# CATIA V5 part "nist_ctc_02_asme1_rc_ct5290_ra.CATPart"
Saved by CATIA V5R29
Part number: NIST Test Case 02 CATIA V5R29 RB
Revision: B
Nomenclature: Test Case 2 Baseline
Property "Modeled By": "Rich Eckenrode, RECON Services.com - Revised by DS"
Property "CAGE Code": "64JW1"
Property "Company": "RECON Services Incorporated"
Bounding box of the stored display mesh (mm): x -340 to 340, y -40 to 820, z -360 to 40
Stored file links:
  E:\users\dgn\TPS V5\Import-export annotations\Step\PMI representation 2015\NIST UC\CTC\nist_ctc_02_asme1_ct5210_rc - V5R29.CATPart
  C:\Program Files\Dassault Systemes\B21\win_b64\reffiles\standard\MetricThickPitch.txt
  E:\users\dgn\TPS V5\Import-export annotations\Step\PMI representation 2015\NIST UC\CTC\nist_ctc_02_asme1_ct5210_rc.CATPart
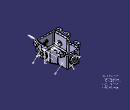
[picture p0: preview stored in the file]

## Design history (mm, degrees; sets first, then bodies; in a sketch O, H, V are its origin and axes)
TTRSSet1
f4a2d38f3ddc11d3a929006094b99c4b_11 "CATTPSSet"
Set1 "MBD_AB"
  Point1: (0, 695.6661, 0), in AxisSystem2
  Point2: (-180, 65.6661, 0), in AxisSystem2
  Point3: (180, 65.6661, 0), in AxisSystem2
  Point4 to Point7: stored without definition
  Point8 "Point.4-c1": (0, 0, -50), in AxisSystem2
Set2 "MBD_A"
  Sketch1 on face of Pad1 from Sketch3.L1, origin (0, 0, 0), H (1, 0, 0), V (0, -0.0349, 0.9994)
    line L1 (180, -29.9817) -> (180, -99.9817)
    point P1 (180, -29.9817)
    length L1 = 70
    distance V L1 = 180
    distance H P1 = 29.9817
    vertical: L1 V
Set3 "MBD_B"
  Point9: type Center, Curve edge of Split1
  AxisSystem1: origin (0, 812, -140), X (1, 0, 0), Y (0, 0, -1), Z (0, 1, 0)
  Sketch2 on face of Hole3, origin (0, 812, 0), H (-1, 0, 0), V (0, 0, 1)
    circle A1 centre (0, -140) radius 42.5
    point P1 (0, -140)
    radius A1 = 42.5
    coincidence: P1 V
  Fill1: Boundary Sketch2
  Split1: ToCut Fill1, Cutting edge [face of Hole3 | face of Hole3]
Set4 "MBD_ABC"
  AxisSystem2: origin (0, 9.7778, -330), X (-1, 0, 0), Y (0, 1, 0), Z (0, 0, -1)
Set5 "MBD_C"
  Point10: type Center, Curve edge [face of Mirror1 | face of Mirror1]
  AxisSystem3: origin (302, 97, 40), X (0, -1, 0), Y (1, 0, 0), Z (0, 0, 1)
  Point11: type Center, Curve edge [face of Pad1 | face of Hole10]
  AxisSystem4: origin (-150, 755, 0), X (0, -1, 0), Y (1, 0, 0), Z (0, 0, 1)
Body1 (main body)
  Sketch3 on xy-plane, origin (0, 0, 0), H (1, 0, 0), V (0, 1, 0)
    point P1 (-250, 0)
    line L1 (-250, 0) -> (250, 0)
    line L2 (250, 0) -> (250, 400)
    line L3 (-250, 400) -> (-250, 0)
    line L4 (-175, 780) -> (175, 780)
    line L5 (175, 780) -> (175, 530)
    line L6 (-175, 530) -> (-175, 780)
    line L7 (175, 530) -> (250, 400)
    line L8 (-250, 400) -> (-175, 530)
    distance L3 L2 = 500
    distance L3 V = 250
    length L2 = 400
    length L3 = 400
    distance L6 L5 = 350
    distance L6 V = 175
    length L5 = 250
    length L6 = 250
    distance L4 L1 = 780
    coincidence: P1 H
    horizontal: L1 H, L4 H
    vertical: L2 V, L3 V, L5 V, L6 V
  Pad1: profile Sketch3, direction (0, 0, -1), length 330
  Draft1: Angle -2, Neutral start face of Pad1, PullDir start face of Pad1, SupportToDraft (face of Pad1 from Sketch3.L1; face of Pad1 from Sketch3.L2; face of Pad1 from Sketch3.L7; face of Pad1 from Sketch3.L5; face of Pad1 from Sketch3.L4; face of Pad1 from Sketch3.L6; face of Pad1 from Sketch3.L8; face of Pad1 from Sketch3.L3)
  Shell1: ExtOffset 0, Face start face of Pad1, IntOffset 40
  Sketch4 on zx-plane, origin (0, 0, 0), H (-1, 0, 0), V (0, 0, 1)
    circle A1 centre (0, -140) radius 100
    point P1 (0, -140)
    distance P1 H = 140
    radius A1 = 100
    coincidence: P1 V
  Sketch5 on yz-plane, origin (0, 0, 0), H (0, 1, 0), V (0, 0, 1)
    point P1 (200, -185)
    ellipse A1 centre (200, -185) semi-axes 120, 90 rotation 0
    distance P1 H = 185
    "Radius" A1 = 120
    distance P1 V = 200
  Pad2: profile Sketch4, direction along zx-plane reversed, length 40, opposite side length 20
  Pad3: profile Sketch4, direction (0, 1, 0), length 750, opposite side length -820
  Pad4: profile Sketch5, direction (1, 0, 0), length 230, opposite side length -265
  Pad5: profile Sketch5, direction (1, 0, 0), length -230, opposite side length 265
  Sketch6 on start face of Pad1, origin (0, 0, 0), H (1, 0, 0), V (0, 1, 0)
    line L1 (-163, 707.9854) -> (-265, 690)
    point P2 (-265, 690)
    line L2 (-265, 690) -> (-265, 574)
    line L3 (-265, 574) -> (-163, 556.0146)
    line L4 (-163, 556.0146) -> (-163, 707.9854)
    line L5 (-235, 368.5143) -> (-340, 350)
    point P5 (-340, 350)
    line L6 (-340, 350) -> (-340, 260)
    point P6 (-340, 260)
    line L7 (-340, 260) -> (-305, 253.8286)
    line L8 (-305, 253.8286) -> (-305, 146.1714)
    line L9 (-305, 146.1714) -> (-340, 140)
    point P9 (-340, 140)
    line L10 (-340, 140) -> (-340, 50)
    line L11 (-340, 50) -> (-235, 31.4857)
    circle A1 centre (-227, 635) radius 11
    point P11 (-227, 635)
    reference projected line E1 (-100, -40) -> (100, -40) from edge [end face of Pad2 | face of Pad2 from Sketch4.A1]
    line L12 (-235, 368.5143) -> (-235, 31.4857)
    circle A2 centre (-302, 302) radius 11
    point P14 (-302, 302)
    circle A3 centre (-302, 97) radius 11
    point P15 (-302, 97)
    reference projected line E2 (-250, 0) -> (250, 0) from edge [face of Pad1 from Sketch3.L1 | start face of Pad1]
    distance P9 P6 = 120
    length L2 = 116
    length L6 = 90
    length L10 = 90
    distance H P5 = 350
    distance H P2 = 690
    angle L1 L2 = 100
    angle L2 L3 = 100
    distance E1 P11 = 675
    distance V P11 = 227
    radius A1 = 11
    distance V L2 = 265
    distance V L6 = 340
    angle L5 L6 = 100
    angle L6 L7 = 100
    angle L9 L10 = 100
    angle L10 L11 = 100
    distance L6 L8 = 35
    distance V P15 = 302
    distance V P14 = 302
    distance P14 P15 = 205
    radius A2 = 11
    radius A3 = 11
    distance P15 E2 = 97
    distance V L12 = 235
    distance V L4 = 163
    vertical: L2 V, L4 V, L6 V, L8 V, L10 V, L12 V
    coincidence: P9 L6
  Pad6: profile Sketch6, direction (0, 0, 1), length 40, mirrored extent
  Draft2: Angle 5, Neutral face of Pad6 from Sketch6.L10, PullDir face of Pad6 from Sketch6.L10, SupportToDraft start face of Pad6
  Draft3: Angle 5, Neutral face of Pad6 from Sketch6.L2, PullDir face of Pad6 from Sketch6.L10, SupportToDraft start face of Pad6
  Mirror1: of Pad6, Draft2, Draft3, about yz-plane
  Sketch7 on start face of Pad1, origin (0, 0, 0), H (1, 0, 0), V (0, 1, 0)
    line L1 (-195, 728.4018) -> (195, 728.4018)
    line L2 (195, 524.7588) -> (-195, 524.7588)
    line L3 (-195, 524.7588) -> (-195, 728.4018)
    line L4 (-270, 397.2577) -> (270, 397.2577)
    line L5 (270, -27.7368) -> (-270, -27.7368)
    line L6 (-270, -27.7368) -> (-270, 397.2577)
    line L7 (195, 524.7588) -> (195, 728.4018)
    line L8 (270, -27.7368) -> (270, 397.2577)
    distance V L3 = 195
    distance V L6 = 270
    horizontal: L1 H, L2 H, L4 H, L5 H
    vertical: L3 V, L6 V
    symmetry: L3 L7 V, L6 L8 V
  Pocket1: profile Sketch7, direction (0, 0, 1), through (limit type 6)
  Draft4: Angle 3, Neutral end face of Pad6, PullDir edge [face of Mirror1 | face of Mirror1], SupportToDraft (face of Pad6 from Sketch6.L1; face of Pad6 from Sketch6.L2; face of Pad6 from Sketch6.L3; face of Pad6 from Sketch6.L5; face of Pad6 from Sketch6.L6; face of Pad6 from Sketch6.L8; face of Pad6 from Sketch6.L9; face of Pad6 from Sketch6.L10; face of Pad6 from Sketch6.L7; face of Pad6 from Sketch6.L11; face of Mirror1; face of Mirror1; face of Mirror1; face of Mirror1; face of Mirror1; face of Mirror1; face of Mirror1; face of Mirror1; face of Mirror1; face of Mirror1)
  Sketch8 on face of Pocket1, origin (0, 0, 0), H (1, 0, 0), V (0, 1, 0)
    construction line L1 (-309.7798, 20) -> (337.0255, 20)
    point P3 (35, 20)
    point P4 (110, 20)
    point P5 (185, 20)
    construction line L2 (230, 491.1929) -> (230, -71.1929)
    construction line L3 (207.3038, 760) -> (-244.515, 760)
    axis line L4 (155, 816.2891) -> (155, 460.0193)
    point P12 (230, 60)
    point P13 (230, 135)
    point P14 (230, 210)
    point P15 (230, 285)
    point P16 (230, 360)
    point P17 (155, 560)
    point P18 (155, 635)
    point P19 (155, 710)
    point P20 (110, 760)
    point P21 (35, 760)
    point P22 (207, 435)
    point P23 (169, 500)
    point P24 (-35, 20)
    point P25 (-110, 20)
    point P26 (-185, 20)
    point P27 (-230, 60)
    point P28 (-230, 135)
    point P29 (-230, 210)
    point P30 (-230, 285)
    point P31 (-230, 360)
    point P32 (-155, 560)
    point P33 (-155, 635)
    point P34 (-155, 710)
    point P35 (-110, 760)
    point P36 (-35, 760)
    point P37 (-207, 435)
    point P38 (-169, 500)
    distance L1 H = 20
    distance V P3 = 35
    distance V P4 = 110
    distance V P5 = 185
    distance V L2 = 230
    distance V L4 = 155
    distance V P21 = 35
    distance V P20 = 110
    distance L1 P12 = 40
    distance L1 P13 = 115
    distance L1 P14 = 190
    distance L1 P15 = 265
    distance L1 P16 = 340
    distance L1 P22 = 415
    distance L1 P23 = 480
    distance L1 P17 = 540
    distance L1 P18 = 615
    distance L1 P19 = 690
    distance V P22 = 207
    distance V P23 = 169
    distance L1 L3 = 740
    horizontal: L1 H, L3 H
    coincidence: P3 L1, P4 L1, P5 L1, P12 L2, P13 L2, P15 L2, P16 L2, P17 L4, P18 L4, P19 L4, P20 L3, P21 L3
    vertical: L2 V, L4 V
    midpoint: P14 L2
    symmetry: P3 P24 V, P4 P25 V, P5 P26 V, P12 P27 V, P13 P28 V, P14 P29 V, P15 P30 V, P16 P31 V, P17 P32 V, P18 P33 V, P19 P34 V, P20 P35 V, P21 P36 V, P22 P37 V, P23 P38 V
  Sketch9 on xy-plane, origin (35, 0, 0), H (1, 0, 0), V (0, 1, 0)
    point P1 (0, 20)
    reference projected point E1 (0, 20) from Sketch8.P3
    coincidence: E1 P1
  Hole1: placed by Sketch9, at (35, 20, 0) direction (0, 0, -1), diameter 10.1, depth 30, V-bottom angle 118
  UserPattern1: of Hole1, copies 30, at the points of Sketch8
  Sketch10 on end face of Pad2, origin (0, -40, -140), H (1, 0, 0), V (0, 0, 1)
    point P1 (0, 0)
    reference intersected line E1 through (0, 0) direction (0, 1) from yz-plane
    reference intersected line E2 through (0, 140) direction (-1, 0) from xy-plane
    distance E1 P1 = 0
    distance E2 P1 = 140
  Hole2: placed by Sketch10, at (0, -40, -140) direction (0, 1, 0), diameter 40, depth 100, counterbore diameter 120, counterbore depth 8
  Sketch11 on start face of Pad3, origin (0, 820, -140), H (1, 0, 0), V (0, 0, -1)
    point P1 (0, 0)
    reference intersected line E1 through (0, 0) direction (0, 1) from yz-plane
    reference intersected line E2 through (0, -140) direction (1, 0) from xy-plane
    distance P1 E1 = 0
    distance E2 P1 = 140
  Hole3: placed by Sketch11, at (0, 820, -140) direction (0, -1, 0), diameter 40, depth 100, counterbore diameter 120, counterbore depth 8
  Sketch12 on face of Hole2, origin (0, -32, 0), H (1, 0, 0), V (0, 0, 1)
    circle A1 centre (0, -140) radius 57.5
    point P1 (0, -140)
    radius A1 = 57.5
    distance H P1 = 140
    coincidence: P1 V
  Pocket2: profile Sketch12, direction (0, 1, 0), length 57, opposite side length -100
  Pocket3: profile Sketch12, direction (0, -1, 0), length -700, opposite side length 787
  Sketch13 on start face of Pocket3, origin (0, 755, 0), H (1, 0, 0), V (0, 0, 1)
    circle A1 centre (0, -140) radius 37.5
    point P1 (0, -140)
    distance P1 H = 140
    radius A1 = 37.5
    coincidence: P1 V
  Pocket4: profile Sketch13, direction (0, 1, 0), length 8
  Sketch14 on end face of Pocket2, origin (0, 25, 0), H (-1, 0, 0), V (0, 0, 1)
    circle A1 centre (0, -140) radius 37.5
    point P1 (0, -140)
    distance P1 H = 140
    radius A1 = 37.5
    coincidence: P1 V
  Pocket5: profile Sketch14, direction (0, -1, 0), length 8
  Sketch15 on start face of Pad4, origin (265, 195.5622, -179.7588), H (0, 1, 0), V (0, 0, 1)
    point P1 (4.4378, -5.2412)
    reference intersected line E1 through (-195.5622, 0) direction (0, 1) from zx-plane
    reference intersected line E2 through (0, 179.7588) direction (-1, 0) from xy-plane
    distance P1 E1 = 200
    distance E2 P1 = 185
  Hole4: placed by Sketch15, at (265, 200, -185) direction (-1, 0, 0), diameter 52, depth 100, counterbore diameter 100, counterbore depth 8
  Sketch16 on start face of Pad5, origin (-265, 207.8851, -185), H (0, 1, 0), V (0, 0, -1)
    point P1 (-7.8851, 0)
    reference intersected line E1 through (0, -185) direction (1, 0) from xy-plane
    reference intersected line E2 through (-207.8851, 0) direction (0, 1) from zx-plane
    distance P1 E1 = 185
    distance E2 P1 = 200
  Hole5: placed by Sketch16, at (-265, 200, -185) direction (1, 0, 0), diameter 52, depth 100, counterbore diameter 100, counterbore depth 8
  Sketch17 on face of Hole5, origin (-257, 0, 0), H (0, -1, 0), V (0, 0, 1)
    circle A1 centre (-200, -185) radius 57.5
    point P1 (-200, -185)
    radius A1 = 57.5
    distance V P1 = 200
    distance H P1 = 185
  Pocket6: profile Sketch17, direction (-1, 0, 0), length -32, opposite side length 100
  Pocket7: profile Sketch17, direction (-1, 0, 0), length -400, opposite side length 482
  Plane1: type Offset, RefPlane zx-plane, Offset 200
  Plane2: type Offset, RefPlane xy-plane, Offset -185
  Sketch18 on start face of Pad4, origin (265, 0, 0), H (0, 1, 0), V (0, 0, 1)
    point P1 (112, -185)
    point P2 (126.83, -145)
    point P3 (171.1, -117)
    point P4 (228.9, -117)
    point P5 (273.17, -145)
    point P6 (288, -185)
    point P7 (273.17, -225)
    point P8 (228.9, -253)
    point P9 (171.1, -253)
    point P10 (126.83, -225)
    reference intersected line E1 through (0, -185) direction (-1, 0) from Plane2
    reference intersected line E2 through (0, -185) direction (-1, 0) from Plane2
    reference intersected line E3 through (0, -185) direction (-1, 0) from Plane2
    reference intersected line E4 through (0, -185) direction (-1, 0) from Plane2
    reference intersected line E5 through (0, -185) direction (-1, 0) from Plane2
    reference intersected line E6 through (0, -185) direction (-1, 0) from Plane2
    reference intersected line E7 through (0, -185) direction (-1, 0) from Plane2
    reference intersected line E8 through (0, -185) direction (-1, 0) from Plane2
    reference intersected line E9 through (0, -185) direction (-1, 0) from Plane2
    reference intersected line E10 through (0, -185) direction (-1, 0) from Plane2
    reference intersected line E11 through (200, 0) direction (0, 1) from Plane1
    reference intersected line E12 through (200, 0) direction (0, 1) from Plane1
    reference intersected line E13 through (200, 0) direction (0, 1) from Plane1
    reference intersected line E14 through (200, 0) direction (0, 1) from Plane1
    reference intersected line E15 through (200, 0) direction (0, 1) from Plane1
    reference intersected line E16 through (200, 0) direction (0, 1) from Plane1
    reference intersected line E17 through (200, 0) direction (0, 1) from Plane1
    reference intersected line E18 through (200, 0) direction (0, 1) from Plane1
    reference intersected line E19 through (200, 0) direction (0, 1) from Plane1
    reference intersected line E20 through (200, 0) direction (0, 1) from Plane1
    distance E1 P1 = 0
    distance E2 P6 = 0
    distance E3 P5 = 40
    distance E4 P7 = 40
    distance E5 P4 = 68
    distance E6 P8 = 68
    distance E7 P9 = 68
    distance E8 P10 = 40
    distance E9 P2 = 40
    distance E10 P3 = 68
    distance E11 P4 = 28.9
    distance E12 P3 = 28.9
    distance E13 P2 = 73.17
    distance E14 P1 = 88
    distance E15 P5 = 73.17
    distance E16 P6 = 88
    distance E17 P7 = 73.17
    distance E18 P8 = 28.9
    distance E19 P9 = 28.9
    distance E20 P10 = 73.17
  Sketch19 on start face of Pad4, origin (265, 296.9999, -181.291), H (0, 1, 0), V (0, 0, 1)
    point P1 (-8.9999, -3.709)
    reference projected point E1 (-8.9999, -3.709) from Sketch18.P6
    coincidence: E1 P1
  Hole6: placed by Sketch19, at (265, 288, -185) direction (-1, 0, 0), diameter 8.38, depth 25, V-bottom angle 118
  UserPattern2: of Hole6, copies 10, at the points of Sketch18
  Sketch20 on start face of Pad5, origin (-265, 288, -185), H (0, 1, 0), V (0, 0, -1)
    point P1 (0, 0)
    reference projected point E1 (0, 0) from Sketch18.P6
    coincidence: E1 P1
  Hole7: placed by Sketch20, at (-265, 288, -185) direction (1, 0, 0), diameter 8.38, depth 25, V-bottom angle 118
  UserPattern3: of Hole7, copies 10, at the points of Sketch18
  Draft5: Angle 3, Neutral end face of Pad2, PullDir end face of Pad2, SupportToDraft face of Pad2 from Sketch4.A1
  Draft6: Angle 3, Neutral start face of Pad3, PullDir start face of Pad3, SupportToDraft face of Pad3 from Sketch4.A1
  Draft7: Angle 3, Neutral start face of Pad5, PullDir start face of Pad5, SupportToDraft face of Pad5 from Sketch5.A1
  Draft8: Angle 3, Neutral start face of Pad4, PullDir start face of Pad4, SupportToDraft face of Pad4 from Sketch5.A1
  Sketch21 on end face of Pad1, origin (0, 0, -330), H (1, 0, 0), V (0, -1, 0)
    line L1 (-135, -115) -> (135, -115)
    line L2 (135, -115) -> (135, -365)
    line L3 (-135, -365) -> (-135, -115)
    line L4 (-82.5, -465) -> (82.5, -465)
    point P5 (-82.5, -465)
    line L5 (135, -365) -> (82.5, -465)
    line L6 (-135, -365) -> (-82.5, -465)
    line L7 (-89.0832, -355.6518) -> (-57.5481, -415.7187)
    point P7 (-95.1571, -344.0825)
    point P8 (-42.6571, -444.0825)
    construction line L8 (-135, -365) -> (-95.1571, -344.0825)
    construction line L9 (-82.5, -465) -> (-42.6571, -444.0825)
    line L10 (89.0832, -355.6518) -> (57.5481, -415.7187)
    point P9 (95.1571, -344.0825)
    point P10 (42.6571, -444.0825)
    construction line L11 (135, -365) -> (95.1571, -344.0825)
    construction line L12 (82.5, -465) -> (42.6571, -444.0825)
    line L13 (-50.4649, -420) -> (50.4649, -420)
    point P11 (-82.5, -420)
    point P12 (82.5, -420)
    construction line L14 (-82.5, -465) -> (-82.5, -420)
    construction line L15 (82.5, -465) -> (82.5, -420)
    line L16 (90, -351.9332) -> (90, -168)
    point P13 (90, -365)
    point P14 (90, -115)
    construction line L17 (135, -365) -> (90, -365)
    construction line L18 (135, -115) -> (90, -115)
    line L19 (-82, -160) -> (82, -160)
    line L20 (-90, -168) -> (-90, -351.9332)
    point P15 (-90, -115)
    point P16 (-90, -365)
    construction line L21 (-135, -115) -> (-90, -115)
    construction line L22 (-135, -365) -> (-90, -365)
    arc A1 centre (-82, -351.9332) radius 8 from (-90, -351.9332) to (-89.0832, -355.6518) ccw
    arc A2 centre (-50.4649, -412) radius 8 from (-57.5481, -415.7187) to (-50.4649, -420) ccw
    arc A3 centre (50.4649, -412) radius 8 from (50.4649, -420) to (57.5481, -415.7187) ccw
    arc A4 centre (82, -351.9332) radius 8 from (90, -351.9332) to (89.0832, -355.6518) cw
    arc A5 centre (82, -168) radius 8 from (90, -168) to (82, -160) ccw
    arc A6 centre (-82, -168) radius 8 from (-82, -160) to (-90, -168) ccw
    length L2 = 250
    distance L1 L4 = 350
    length L3 = 250
    distance L3 L2 = 270
    distance V L2 = 135
    length L4 = 165
    distance V P5 = 82.5
    distance L6 L7 = 45
    distance L5 L10 = 45
    distance L4 L13 = 45
    distance L2 L16 = 45
    distance L3 L20 = 45
    distance L1 L19 = 45
    radius A1 = 8
    radius A2 = 8
    radius A3 = 8
    radius A4 = 8
    radius A5 = 8
    radius A6 = 8
    distance L1 H = 115
    horizontal: L1 H, L4 H
    vertical: L2 V, L3 V
    perpendicularity: L8 L6, L8 L7, L9 L6, L9 L7, L11 L5, L11 L10, L12 L5, L12 L10, L14 L4, L14 L13, L15 L4, L15 L13, L17 L2, L17 L16, L18 L2, L18 L16, L21 L3, L21 L20, L22 L3, L22 L20
    coincidence: P13 L16, P9 L10, P10 L10, P12 L13, P11 L13, P8 L7, P7 L7, P16 L20, P15 L20, P14 L16
    tangency: A1 L20, A1 L7, A2 L7, A2 L13, A3 L13, A3 L10, A4 L16, A4 L10, A5 L16, A5 L19, A6 L19, A6 L20
  Pad7: profile Sketch21, direction (0, 0, -1), length 30
  Sketch22 on end face of Pad7, origin (0, 0, -360), H (1, 0, 0), V (0, -1, 0)
    line L1 (91, -141) -> (-91, -141)
    line L2 (109, -159) -> (109, -354.1521)
    line L3 (55.9048, -439) -> (-55.9048, -439)
    line L4 (-109, -354.1521) -> (-109, -159)
    reference projected line E1 (135, -115) -> (-135, -115) from edge [face of Pad7 | face of Pad7]
    reference projected line E2 (135, -365) -> (135, -115) from edge [face of Pad7 | face of Pad7]
    reference projected line E3 (-82.5, -465) -> (82.5, -465) from edge [face of Pad7 | face of Pad7]
    reference projected line E4 (-135, -115) -> (-135, -365) from edge [face of Pad7 | face of Pad7]
    line L5 (106.9372, -362.5191) -> (71.842, -429.367)
    line L6 (-71.842, -429.367) -> (-106.9372, -362.5191)
    reference projected line E5 (82.5, -465) -> (135, -365) from edge [face of Pad7 | face of Pad7]
    reference projected line E6 (-135, -365) -> (-82.5, -465) from edge [face of Pad7 | face of Pad7]
    arc A1 centre (91, -159) radius 18 from (109, -159) to (91, -141) ccw
    arc A2 centre (-91, -159) radius 18 from (-91, -141) to (-109, -159) ccw
    arc A3 centre (-91, -354.1521) radius 18 from (-109, -354.1521) to (-106.9372, -362.5191) ccw
    arc A4 centre (-55.9048, -421) radius 18 from (-71.842, -429.367) to (-55.9048, -439) ccw
    arc A5 centre (55.9048, -421) radius 18 from (55.9048, -439) to (71.842, -429.367) ccw
    arc A6 centre (91, -354.1521) radius 18 from (106.9372, -362.5191) to (109, -354.1521) ccw
    line L7 (101, -159) -> (101, -354.1521)
    point P19 (101, -159)
    point P20 (101, -354.1521)
    construction line L8 (109, -159) -> (101, -159)
    construction line L9 (109, -354.1521) -> (101, -354.1521)
    line L10 (91, -149) -> (-91, -149)
    point P21 (91, -149)
    point P22 (-91, -149)
    construction line L11 (91, -141) -> (91, -149)
    construction line L12 (-91, -141) -> (-91, -149)
    line L13 (-101, -354.1521) -> (-101, -159)
    point P23 (-101, -354.1521)
    point P24 (-101, -159)
    construction line L14 (-109, -354.1521) -> (-101, -354.1521)
    construction line L15 (-109, -159) -> (-101, -159)
    line L16 (-64.7588, -425.6483) -> (-99.854, -358.8004)
    point P25 (-64.7588, -425.6483)
    point P26 (-99.854, -358.8004)
    construction line L17 (-71.842, -429.367) -> (-64.7588, -425.6483)
    construction line L18 (-106.9372, -362.5191) -> (-99.854, -358.8004)
    line L19 (55.9048, -431) -> (-55.9048, -431)
    point P27 (55.9048, -431)
    point P28 (-55.9048, -431)
    construction line L20 (55.9048, -439) -> (55.9048, -431)
    construction line L21 (-55.9048, -439) -> (-55.9048, -431)
    line L22 (99.854, -358.8004) -> (64.7588, -425.6483)
    point P29 (99.854, -358.8004)
    point P30 (64.7588, -425.6483)
    construction line L23 (106.9372, -362.5191) -> (99.854, -358.8004)
    construction line L24 (71.842, -429.367) -> (64.7588, -425.6483)
    arc A7 centre (91, -159) radius 10 from (101, -159) to (91, -149) ccw
    arc A8 centre (-91, -159) radius 10 from (-91, -149) to (-101, -159) ccw
    arc A9 centre (-91, -354.1521) radius 10 from (-101, -354.1521) to (-99.854, -358.8004) ccw
    arc A10 centre (-55.9048, -421) radius 10 from (-64.7588, -425.6483) to (-55.9048, -431) ccw
    arc A11 centre (55.9048, -421) radius 10 from (55.9048, -431) to (64.7588, -425.6483) ccw
    arc A12 centre (91, -354.1521) radius 10 from (101, -354.1521) to (99.854, -358.8004) cw
    distance E1 L1 = 26
    distance E2 L2 = 26
    distance L3 E3 = 26
    distance L4 E4 = 26
    distance E5 L5 = 26
    distance L6 E6 = 26
    radius A1 = 18
    radius A2 = 18
    radius A3 = 18
    radius A5 = 18
    radius A6 = 18
    distance L2 L7 = 8
    distance L1 L10 = 8
    distance L4 L13 = 8
    distance L6 L16 = 8
    distance L3 L19 = 8
    distance L5 L22 = 8
    radius A7 = 10
    radius A8 = 10
    radius A9 = 10
    radius A10 = 10
    radius A11 = 10
    radius A12 = 10
    radius A4 = 18
    horizontal: L1 H, L3 H
    vertical: L2 V, L4 V
    tangency: A1 L2, A1 L1, A2 L1, A2 L4, A3 L4, A3 L6, A4 L6, A4 L3, A5 L3, A5 L5, A6 L5, A6 L2, A7 L7, A8 L10, A8 L13, A9 L13, A9 L16, A10 L16, A10 L19, A11 L19, A11 L22, A12 L7, A12 L22
    perpendicularity: L8 L2, L8 L7, L9 L2, L9 L7, L11 L1, L11 L10, L12 L1, L12 L10, L14 L4, L14 L13, L15 L4, L15 L13, L17 L6, L17 L16, L18 L6, L18 L16, L20 L3, L20 L19, L21 L3, L21 L19, L23 L5, L23 L22, L24 L5, L24 L22
    coincidence: P19 L7, P21 L10, L10 P22, L13 P24, L13 P23, L16 P26, L16 P25, L19 P28, L19 P27, L22 P30, L7 P20, L22 P29
  Pocket8: profile Sketch22, direction (0, 0, 1), length 8
  Sketch23 on end face of Pad7, origin (0, 0, -360), H (1, 0, 0), V (0, -1, 0)
    construction line L1 (147.8122, -128) -> (-168.3513, -128)
    construction line L2 (122, -83.3568) -> (122, -419.3374)
    construction line L3 (-122, -77.561) -> (-122, -413.5541)
    construction line L4 (122, -452) -> (-122, -452)
    point P7 (122, -452)
    point P8 (-122, -452)
    reference projected line E1 (109, -354.1521) -> (109, -159) from edge [end face of Pad7 | face of Pocket8 from Sketch22.L2]
    reference projected line E2 (-109, -159) -> (-109, -354.1521) from edge [end face of Pad7 | face of Pocket8 from Sketch22.L4]
    reference projected line E3 (-55.9048, -439) -> (55.9048, -439) from edge [end face of Pad7 | face of Pocket8 from Sketch22.L3]
    reference projected line E4 (91, -141) -> (-91, -141) from edge [end face of Pad7 | face of Pocket8 from Sketch22.L1]
    point P9 (25, -128)
    point P10 (74, -128)
    point P11 (122, -128)
    point P12 (-25, -128)
    point P13 (-74, -128)
    point P14 (-122, -128)
    point P15 (-122, -176)
    point P16 (-122, -224)
    point P17 (-122, -272)
    point P18 (-122, -320)
    point P19 (-25, -452)
    point P20 (25, -452)
    point P21 (122, -320)
    point P22 (122, -272)
    point P23 (122, -224)
    point P24 (122, -176)
    construction line L5 (0, -44.6123) -> (0, -544.8239)
    point P25 (0, -44.6123)
    point P27 (74.6423, -452)
    point P28 (122, -361.795)
    point P29 (97.9523, -407.6)
    point P30 (-74.6423, -452)
    point P31 (-122, -361.795)
    point P32 (-97.9523, -407.6)
    reference projected line E5 (91, -141) -> (-91, -141) from edge [end face of Pad7 | face of Pocket8 from Sketch22.L1]
    reference projected line E6 (91, -141) -> (-91, -141) from edge [end face of Pad7 | face of Pocket8 from Sketch22.L1]
    distance E1 L2 = 13
    distance L3 E2 = 13
    distance E3 L4 = 13
    distance E4 L1 = 13
    distance P11 P24 = 48
    distance P24 P23 = 48
    distance P23 P22 = 48
    distance P22 P21 = 48
    distance P14 P15 = 48
    distance P15 P16 = 48
    distance P16 P17 = 48
    distance P17 P18 = 48
    distance L5 P20 = 25
    distance L5 P19 = 25
    distance L5 P9 = 25
    distance L5 P12 = 25
    distance L5 P13 = 74
    distance L5 P10 = 74
    distance E5 P32 = 266.6
    distance P29 E6 = 266.6
    distance L5 P32 = 97.9523
    distance L5 P29 = 97.9523
    distance P21 P28 V = 41.795
    distance P31 P18 = 41.795
    distance P27 L2 = 47.3577
    distance L3 P30 = 47.3577
    horizontal: L1 H, L4 H
    vertical: L2 V, L3 V, L5 V
    coincidence: P7 L2, P8 L3, P9 L1, P10 L1, P11 L2, P11 L1, P12 L1, P13 L1, P14 L3, P14 L1, P15 L3, P16 L3, P17 L3, P18 L3, P19 L4, P20 L4, P21 L2, P22 L2, P23 L2, P24 L2, P25 V, P27 L4, P28 L2, P30 L4, P31 L3
  Sketch24 on end face of Pad7, origin (122, 111.7735, -360), H (1, 0, 0), V (0, -1, 0)
    point P1 (0, -16.2265)
    reference projected point E1 (0, -16.2265) from Sketch23.P11
    coincidence: E1 P1
  Hole8: placed by Sketch24, at (122, 128, -360) direction (0, 0, 1), diameter 8.38, depth 25, V-bottom angle 118
  UserPattern4: of Hole8, copies 22, at the points of Sketch23
  Sketch25 on end face of Pad1, origin (0, 0, -330), H (1, 0, 0), V (0, -1, 0)
    arc A1 centre (0, -286) radius 60 from (35, -334.734) to (35, -237.266) ccw
    point P1 (0, -286)
    line L1 (-20, -196) -> (20, -196)
    line L2 (35, -211) -> (35, -237.266)
    line L3 (-35, -237.266) -> (-35, -211)
    line L4 (35, -334.734) -> (35, -361)
    line L5 (20, -376) -> (-20, -376)
    line L6 (-35, -361) -> (-35, -334.734)
    point P2 (35, -376)
    arc A2 centre (0, -286) radius 60 from (-35, -237.266) to (-35, -334.734) ccw
    arc A3 centre (-20, -361) radius 15 from (-35, -361) to (-20, -376) ccw
    arc A4 centre (20, -361) radius 15 from (20, -376) to (35, -361) ccw
    arc A5 centre (20, -211) radius 15 from (35, -211) to (20, -196) ccw
    arc A6 centre (-20, -211) radius 15 from (-20, -196) to (-35, -211) ccw
    reference projected line E1 (91, -141) -> (-91, -141) from edge [end face of Pad7 | face of Pocket8 from Sketch22.L1]
    radius A3 = 15
    radius A4 = 15
    radius A5 = 15
    radius A6 = 15
    distance L6 L4 = 70
    distance L2 L3 = 70
    distance L1 L5 = 180
    radius A2 = 60
    distance L1 P1 = 90
    distance E1 L1 = 55
    distance V L2 = 35
    coincidence: P1 V, P2 L2, A1 A2, L5 P2, L4 P2
    horizontal: L1 H, L5 H
    vertical: L2 V, L3 V, L4 V, L6 V
    tangency: A3 L6, A3 L5, A4 L5, A4 L4, A5 L2, A5 L1, A6 L1, A6 L3
  Pocket9: profile Sketch25, direction (0, 0, 1), length 100
  Draft9: Angle 3, Neutral end face of Pad7, PullDir end face of Pad7, SupportToDraft (face of Pad7 from Sketch21.L2; face of Pad7 from Sketch21.L5; face of Pad7 from Sketch21.L4; face of Pad7 from Sketch21.L6; face of Pad7 from Sketch21.L3; face of Pad7 from Sketch21.L1; face of Pad7 from Sketch21.L13)
  Fillet1: radius 25, on edge [face of Pad1 from Sketch3.L5 | end face of Pad1]; edge [face of Pad1 from Sketch3.L7 | end face of Pad1]; edge [face of Pad1 from Sketch3.L2 | end face of Pad1]; edge [face of Pad1 from Sketch3.L1 | end face of Pad1]; edge [face of Pad1 from Sketch3.L3 | end face of Pad1]; edge [face of Pad1 from Sketch3.L8 | end face of Pad1]; edge [face of Pad1 from Sketch3.L6 | end face of Pad1]; edge [face of Pad1 from Sketch3.L4 | end face of Pad1]; edge [face of Pad1 from Sketch3.L5 | face of Pad1 from Sketch3.L4]; edge [face of Pad1 from Sketch3.L5 | face of Pad1 from Sketch3.L7]; edge [face of Pad1 from Sketch3.L2 | face of Pad1 from Sketch3.L7]; edge [face of Pad1 from Sketch3.L1 | face of Pad1 from Sketch3.L2]; edge [face of Pad1 from Sketch3.L3 | face of Pad1 from Sketch3.L1]; edge [face of Pad1 from Sketch3.L8 | face of Pad1 from Sketch3.L3]; edge [face of Pad1 from Sketch3.L8 | face of Pad1 from Sketch3.L6]; edge [face of Pad1 from Sketch3.L4 | face of Pad1 from Sketch3.L6]; edge [face of Shell1 | face of Shell1] (x16)
  Fillet2: radius 8, on edge [face of Pad7 from Sketch21.L16 | end face of Pad1]
  Fillet3: radius 10, on edge [face of Pad5 from Sketch5.A1 | face of Pad1 from Sketch3.L3]; edge [face of Pad2 from Sketch4.A1 | face of Pad1 from Sketch3.L1]; edge [face of Pad4 from Sketch5.A1 | face of Pad1 from Sketch3.L2]; edge [face of Pad3 from Sketch4.A1 | face of Pad1 from Sketch3.L4]; edge [face of Pad6 from Sketch6.L1 | face of Pad1 from Sketch3.L6]; edge [start face of Pad6 | face of Pad1 from Sketch3.L6]; edge [face of Pad6 from Sketch6.L1 | start face of Pad6]; edge [face of Pad6 from Sketch6.L2 | face of Pad6 from Sketch6.L1]; edge [face of Pad6 from Sketch6.L2 | start face of Pad6]; edge [face of Pad6 from Sketch6.L3 | face of Pad6 from Sketch6.L2]; edge [face of Pad6 from Sketch6.L3 | face of Pad1 from Sketch3.L6]; edge [face of Pad6 from Sketch6.L5 | face of Pad1 from Sketch3.L3]; edge [start face of Pad6 | face of Pad1 from Sketch3.L3]; edge [face of Pad6 from Sketch6.L5 | start face of Pad6]; edge [face of Pad6 from Sketch6.L6 | face of Pad6 from Sketch6.L5]; edge [face of Pad6 from Sketch6.L6 | start face of Pad6]; edge [face of Pad6 from Sketch6.L7 | face of Pad6 from Sketch6.L6]; edge [face of Pad6 from Sketch6.L7 | start face of Pad6]; edge [face of Pad6 from Sketch6.L7 | face of Pad6 from Sketch6.L8]; edge [start face of Pad6 | face of Pad6 from Sketch6.L8]; edge [face of Pad6 from Sketch6.L9 | face of Pad6 from Sketch6.L8]; edge [face of Pad6 from Sketch6.L9 | start face of Pad6]; edge [face of Pad6 from Sketch6.L10 | face of Pad6 from Sketch6.L9]; edge [face of Pad6 from Sketch6.L10 | start face of Pad6]; edge [face of Pad6 from Sketch6.L11 | face of Pad6 from Sketch6.L10]; edge [face of Pad6 from Sketch6.L11 | face of Pad1 from Sketch3.L3]; edge [face of Mirror1 | face of Pad1 from Sketch3.L2] (x3); edge [face of Mirror1 | face of Mirror1] (x18); edge [face of Mirror1 | face of Pad1 from Sketch3.L5] (x3); edge [face of Pad6 from Sketch6.L3 | start face of Pad6]; edge [face of Pad6 from Sketch6.L11 | start face of Pad6]
  Sketch26 on face of Mirror1, origin (0, 0, 40), H (1, 0, 0), V (0, 1, 0)
    reference projected circle E1 centre (302, 97) radius 11 from edge [face of Mirror1 | face of Mirror1]
    reference projected circle E2 centre (302, 302) radius 11 from edge [face of Mirror1 | face of Mirror1]
    reference projected circle E3 centre (227, 635) radius 11 from edge [face of Mirror1 | face of Mirror1]
    reference projected circle E4 centre (-227, 635) radius 11 from edge [end face of Pad6 | face of Pad6 from Sketch6.A1]
    reference projected circle E5 centre (-302, 302) radius 11 from edge [end face of Pad6 | face of Pad6 from Sketch6.A2]
    reference projected circle E6 centre (-302, 97) radius 11 from edge [end face of Pad6 | face of Pad6 from Sketch6.A3]
    circle A1 centre (302, 97) radius 30
    point P1 (302, 97)
    circle A2 centre (302, 302) radius 30
    point P2 (302, 302)
    circle A3 centre (227, 635) radius 30
    point P3 (227, 635)
    circle A4 centre (-227, 635) radius 30
    point P4 (-227, 635)
    circle A5 centre (-302, 302) radius 30
    point P5 (-302, 302)
    circle A6 centre (-302, 97) radius 30
    point P6 (-302, 97)
    radius A1 = 30
    radius A2 = 30
    radius A3 = 30
    radius A4 = 30
    radius A5 = 30
    radius A6 = 30
    concentricity: P1 E1, P2 E2, P3 E3, P4 E4, P5 E5, P6 E6
  Pocket10: profile Sketch26, direction (0, 0, -1), length 200, opposite side length -81
  Fillet4: radius 6, on edge [face of Pocket1 from Sketch7.L6 | face of Pad1]; edge [face of Pocket1 from Sketch7.L3 | face of Pad1]; edge [face of Pocket1 from Sketch7.L8 | face of Pad1]; edge [face of Pocket1 from Sketch7.L7 | face of Pad1]
  Fillet5: radius 10, on edge [face of Pad7 from Sketch21.L3 | end face of Pad1]; edge [face of Pad7 from Sketch21.L6 | end face of Pad1]; edge [face of Pad7 from Sketch21.L1 | end face of Pad1]; edge [face of Pad7 from Sketch21.L4 | end face of Pad1]; edge [face of Pad7 from Sketch21.L5 | end face of Pad1]; edge [face of Pad7 from Sketch21.L2 | end face of Pad1]
  Sketch27 on face of Pad1, origin (216.5379, 25.9779, 0), H (1, 0, 0), V (0, 1, 0)
    point P1 (-0.5379, -0.9779)
    reference intersected line E1 through (0, -25.9779) direction (-1, 0) from zx-plane
    reference intersected line E2 through (-216.5379, 0) direction (0, 1) from yz-plane
    distance E1 P1 = 25
    distance E2 P1 = 216
  Hole9: placed by Sketch27, at (216, 25, 0) direction (0, 0, -1), diameter 12, depth 25, V-bottom angle 118
  Sketch28 on face of Pad1, origin (-144.2728, 755.1781, 0), H (1, 0, 0), V (0, 1, 0)
    point P1 (-5.7272, -0.1781)
    reference intersected line E1 through (0, -755.1781) direction (-1, 0) from zx-plane
    reference intersected line E2 through (144.2728, 0) direction (0, 1) from yz-plane
    distance E1 P1 = 755
    distance E2 P1 = 150
  Hole10: placed by Sketch28, at (-150, 755, 0) direction (0, 0, -1), diameter 12, depth 25, V-bottom angle 118
  Point12: (0, 9.7778, -330)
